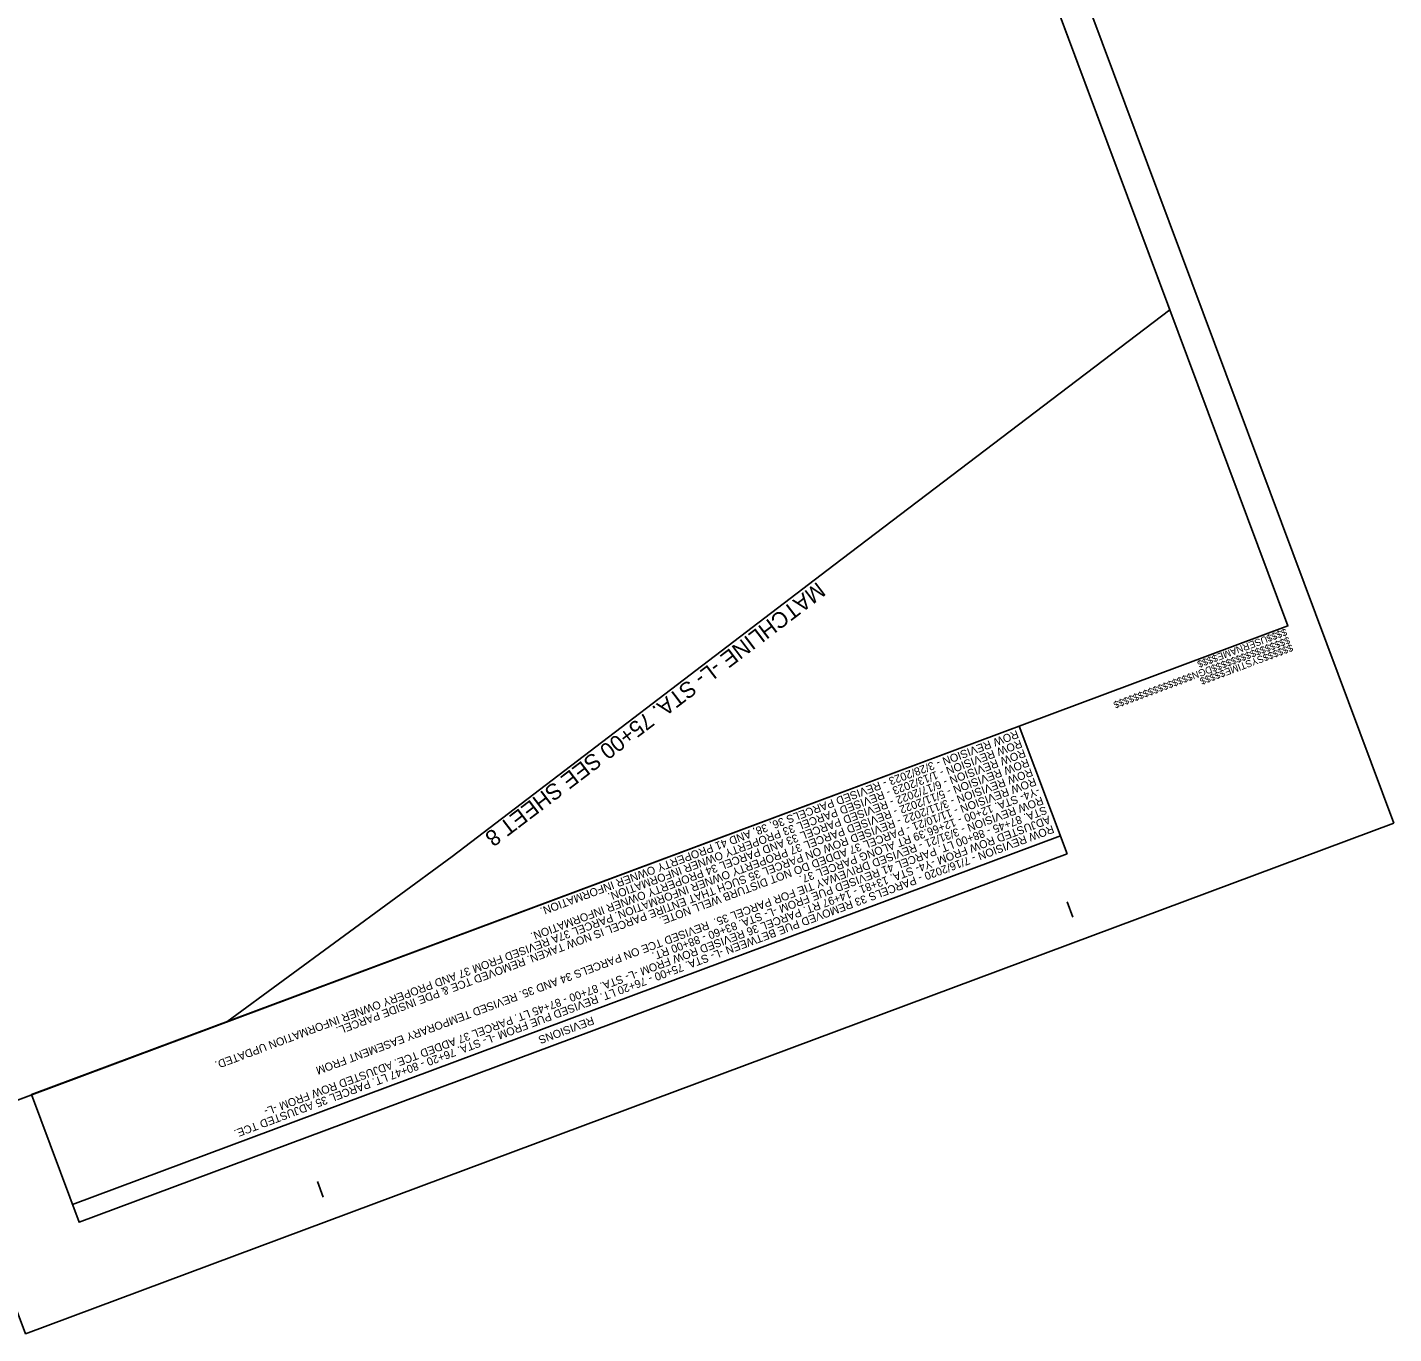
# Model space of a CAD drawing. Extents: x 477774 to 479389, y 493760 to 495720.
# Drawn here: x 478364 to 479389, y 493760 to 494740 of the extents above; entities that cross this region are included whole.
import ezdxf

# ---------------------------------------------------------------- set-up
doc = ezdxf.new("R2010")
doc.units = 0
for name, color, linetype in [('Matchline', 7, 'Continuous'), ('Matchline Text', 7, 'Continuous'), ('Sheet Block Revision CELL', 7, 'Continuous'), ('Sheet Clip Boundary CELL', 7, 'Continuous'), ('Sheet Plan CELL', 7, 'Continuous'), ('Sheet Plot Border Outside CELL', 7, 'Continuous')]:
    doc.layers.add(name, color=color, linetype=linetype)

msp = doc.modelspace()

# ---------------------------------------------------------------- linework, layer by layer
at = {"layer": 'Matchline'}
msp.add_line((478969, 494336.5), (478682.9, 494117.9), dxfattribs=at)
at = {"layer": 'Sheet Block Revision CELL'}
msp.add_line((479138.9, 494133.4), (478398.2, 493856.9), dxfattribs=at)
msp.add_lwpolyline([(479143.9, 494120.1), (478403.1, 493843.6), (478367.4, 493939.4), (479108.1, 494215.8)], close=True, dxfattribs=at)
at = {"layer": 'Sheet Clip Boundary CELL'}
msp.add_lwpolyline([(478513.9, 493994), (478682.9, 494117.9), (478969, 494336.5), (479221.1, 494528), (478936.8, 495289.6), (478873, 495265.8), (478780.8, 495512.7), (478769.7, 495508.6), (478559.2, 495461), (478204.1, 495401.9), (477970.2, 495374), (478033.8, 495202.4), (477871.2, 495141.7), (478325.9, 493923.8)], close=True, dxfattribs=at)
at = {"layer": 'Sheet Plan CELL'}
for p, q in [((479309.5, 494291), (479309.5, 494291)), ((479148.3, 494072.4), (479144, 494084.1)), ((478586.2, 493862.5), (478581.8, 493874.3))]:
    msp.add_line(p, q, dxfattribs=at)
for points in [[(477801.3, 495329.2), (478325.8, 493923.8), (479309.5, 494291), (478785, 495696.3)], [(479309.5, 494291), (478325.9, 493923.8), (477871.2, 495141.7), (478011.8, 495194.2), (477941.9, 495381.6), (478785, 495696.3)]]:
    msp.add_lwpolyline(points, close=True, dxfattribs=at)
at = {"layer": 'Sheet Plot Border Outside CELL'}
msp.add_lwpolyline([(479388.9, 494142.9), (478800.1, 495720.1), (477774.3, 495337.2), (478363, 493760)], close=True, dxfattribs=at)

# ---------------------------------------------------------------- texts
at = {"layer": 'Matchline Text'}
msp.add_text('MATCHLINE -L- STA. 75+00 SEE SHEET 8', height=12, rotation=217.2446, dxfattribs=at).set_placement((478956.7, 494324.5))
at = {"layer": 'Sheet Block Revision CELL'}
for s, p in [('ROW REVISION - 3/28/2023 - REVISED PARCELS 36, 38, AND 41 PROPERTY OWNER INFORMATION. ', (479106.2, 494212.9)), ('ROW REVISION - 1/13/2023 - REVISED PARCEL 33 PROPERTY OWNER INFORMATION. ', (479108.9, 494205.8)), ('ROW REVISION - 6/17/2022 - REVISED PARCEL 33 AND PARCEL 34 PROPERTY OWNER INFORMATION.  ', (479111.5, 494198.7)), ('ROW REVISION - 5/11/2022 - REVISED PARCEL 37 PROPERTY OWNER INFORMATION. PARCEL 37A REVISED FROM 37 AND PROPERY OWNER INFORMATION UPDATED.  ', (479114.2, 494191.6)), ('ROW REVISION - 3/11/2022 - REVISED ROW ON PARCEL 35 SUCH THAT ENTIRE PARCEL IS NOW TAKEN. REMOVED TCE & PDE INSIDE PARCEL. ', (479116.9, 494184.4)), ('ROW REVISION - 11/10/21 - PARCEL 37 ADDED DO NOT DISTURB WELL NOTE. ', (479119.5, 494177.3)), ('ROW REVISION - 3/31/21 - REVISED DRIVEWAY TIE FOR PARCEL 35.  REVISED TCE ON PARCELS 34 AND 35. REVISED TEMPORARY EASEMENT FROM ', (479124.8, 494163.1)), ('-Y4- STA. 12+00 - 12+66.39 RT ALONG PARCEL 37. ', (479122.2, 494170.2)), ('STA. 87+45 - 88+00 LT. PARCEL 41 REVISED PUE FROM -L- STA. 83+60 - 88+00 RT.', (479127.5, 494155.9)), ('ROW REVISION - 7/16/2020 - PARCELS 33 REMOVED PUE BETWEEN -L- STA. 75+00 - 76+20 LT. REVISED PUE FROM -L- STA. 76+20 - 80+47 LT. PARCEL 35 ADJUSTED TCE.', (479132.8, 494141.7)), ('ADJUSTED ROW FROM -Y4- STA. 13+81 - 14+97 RT. PARCEL 36 REVISED ROW FROM -L- STA. 87+00 - 87+45 LT. PARCEL 37 ADDED TCE. ADJUSTED ROW FROM -L- ', (479130.2, 494148.8)), ('REVISIONS', (478787.9, 493998.1))]:
    msp.add_text(s, height=6, rotation=200.469, dxfattribs=at).set_placement(p)
at = {"layer": 'Sheet Plan CELL'}
for s, p in [('$$$$USERNAME$$$$', (479307.7, 494289.2)), ('$$$$$$$$$$$$$$$$DGN$$$$$$$$$$$$$$$$', (479310, 494283)), ('$$$$$$SYSTIME$$$$$', (479312.2, 494277.4))]:
    msp.add_text(s, height=5.25, rotation=200.469, dxfattribs=at).set_placement(p)

doc.saveas('drawing.dxf')
